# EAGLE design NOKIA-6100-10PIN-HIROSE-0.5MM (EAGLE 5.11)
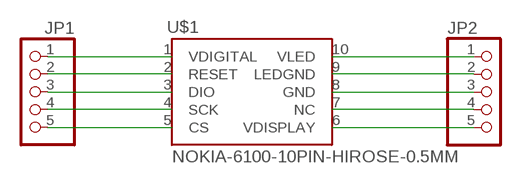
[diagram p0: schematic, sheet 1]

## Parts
JP1  PINHD-1X5  [1X05]
JP2  PINHD-1X5  [1X05]
U$1  NOKIA-6100-10PIN-HIROSE-0.5MM  [NOKIA-6100-10PIN-HIROSE-0.5MM]

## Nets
N$1: JP1.1 U$1.1(VDIGITAL)
N$2: JP1.2 U$1.2(RESET)
N$3: JP1.3 U$1.3(DIO)
N$4: JP1.4 U$1.4(SCK)
N$5: JP1.5 U$1.5(CS)
N$6: JP2.5 U$1.6(VDISPLAY)
N$7: JP2.4 U$1.7(NC)
N$8: JP2.3 U$1.8(GND)
N$9: JP2.2 U$1.9(LEDGND)
N$10: JP2.1 U$1.10(VLED)

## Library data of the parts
JP1 JP2 = pinhead:PINHD-1X5: PIN HEADER
U$1 = trl:NOKIA-6100-10PIN-HIROSE-0.5MM

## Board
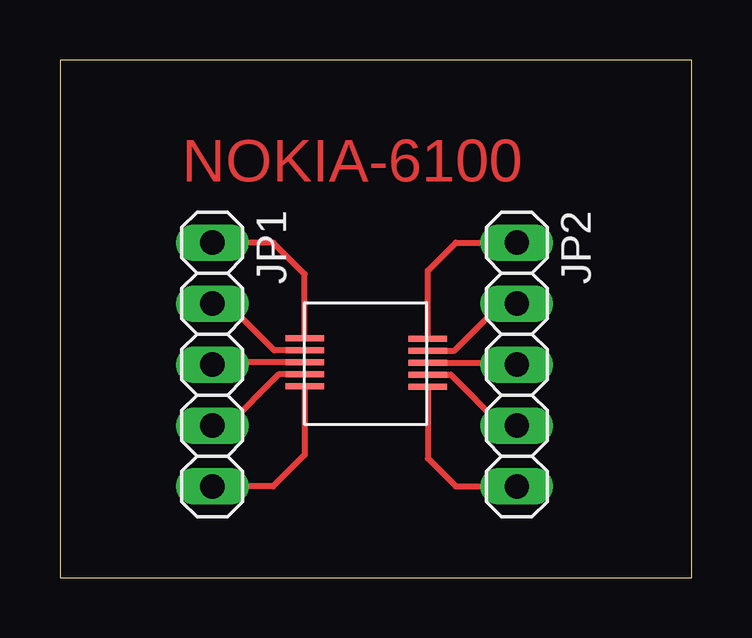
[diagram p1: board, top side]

Size 26.34 x 21.58 mm. Coordinates in mm from the lower left corner, seen from the top.
Outline: 0,0 26.34,0 26.34,21.58 0,21.58 0,0
Copper layers (1*16): Top 0.035mm / dielectric 1.5mm / Bottom 0.035mm
Design rules "default": minimum track width 10mil, minimum drill 24mil, track to track 8mil, track to pad 8mil, pad to pad 8mil, via to via 8mil, smd to smd 8mil, copper to edge 40mil, drill to drill 8mil, minimum pad ring 10mil, minimum via ring 8mil, stop-mask expansion 4mil, vias tented up to drill 0mil, thermal gap 10mil

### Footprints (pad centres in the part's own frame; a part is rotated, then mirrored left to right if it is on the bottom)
1X05 = drill 1.016 long: 1 -5.08,0; 2 -2.54,0; 3 0,0; 4 2.54,0; 5 5.08,0
NOKIA-6100-10PIN-HIROSE-0.5MM = smd 1.6 x 0.25: 1 0.045,3.631; 2 0.045,3.131; 3 0.045,2.631; 4 0.045,2.131; 5 0.045,1.631; 6 5.179,1.623; 7 5.179,2.123; 8 5.179,2.623; 9 5.179,3.123; 10 5.179,3.623

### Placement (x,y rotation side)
JP1  6.35,8.89 270 top
JP2  19.05,8.89 270 top
U$1  10.16,6.35 0 top

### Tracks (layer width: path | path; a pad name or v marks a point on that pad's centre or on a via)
N$1
  Top 0.254: U$1.1 10.21,12.65 8.89,13.97 JP1.1
N$2
  Top 0.254: U$1.2 8.93,9.48 6.99,11.43 JP1.2
N$3
  Top 0.254: U$1.3 6.35,8.98 JP1.3
N$4
  Top 0.254: U$1.4 9.12,8.48 6.99,6.35 JP1.4
N$5
  Top 0.254: U$1.5 10.21,5.12 8.89,3.81 JP1.5
N$6
  Top 0.254: U$1.6 15.34,4.98 16.51,3.81 JP2.5
N$7
  Top 0.254: U$1.7 16.29,8.47 18.41,6.35 JP2.4
N$8
  Top 0.254: U$1.8 18.97,8.97 JP2.3
N$9
  Top 0.254: U$1.9 16.46,9.47 18.41,11.43 JP2.2
N$10
  Top 0.254: U$1.10 15.34,12.8 16.51,13.97 JP2.1

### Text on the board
Top: NOKIA-6100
